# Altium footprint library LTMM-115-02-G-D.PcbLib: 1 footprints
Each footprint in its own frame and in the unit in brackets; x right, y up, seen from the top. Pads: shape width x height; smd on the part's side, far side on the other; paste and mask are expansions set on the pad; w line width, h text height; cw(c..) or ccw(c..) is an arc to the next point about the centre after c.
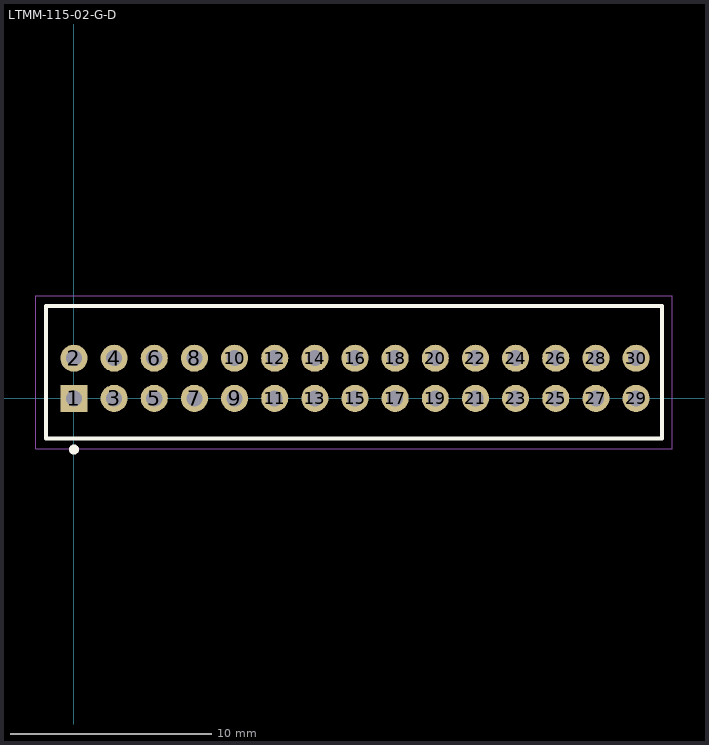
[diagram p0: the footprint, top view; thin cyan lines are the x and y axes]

## LTMM-115-02-G-D [mm] "2.00mm pitch, 30 pin, header; shrouded, PTH"
height 5.33
pads (30):
  rect 1.35x1.35 / inner round 1.35 / far side rect 1.35x1.35 hole 0.8 mask+0: 1(0,0)
  round 1.35 hole 0.8 mask+0: 2(0,2) 3(2,0) 4(2,2) 5(4,0) 6(4,2) 7(6,0) 8(6,2) 9(8,0) 10(8,2) 11(10,0) 12(10,2) 13(12,0) 14(12,2) 15(14,0) 16(14,2) 17(16,0) 18(16,2) 19(18,0) 20(18,2) 21(20,0) 22(20,2) 23(22,0) 24(22,2) 25(24,0) 26(24,2) 27(26,0) 28(26,2) 29(28,0) 30(28,2)
Top Overlay:
  circle w0.25: c0,-2.55 r0.125
  lines w0.2: -1.4,-2 -1.4,4.6 29.3,4.6 29.3,-2 -1.4,-2
Mechanical 12:
  lines w0.001: -1.4,-2 -1.4,4.6 29.3,4.6 29.3,-2 -1.4,-2
Mechanical 13:
  lines w0.1: -1.4,-2 -1.4,4.6 29.3,4.6 29.3,-2 -1.4,-2
  text ".Designator" at 0.254,0.254 h1.52
Mechanical 15:
  lines w0.05: -1.9,-2.5 -1.9,5.1 29.8,5.1 29.8,-2.5 -1.9,-2.5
